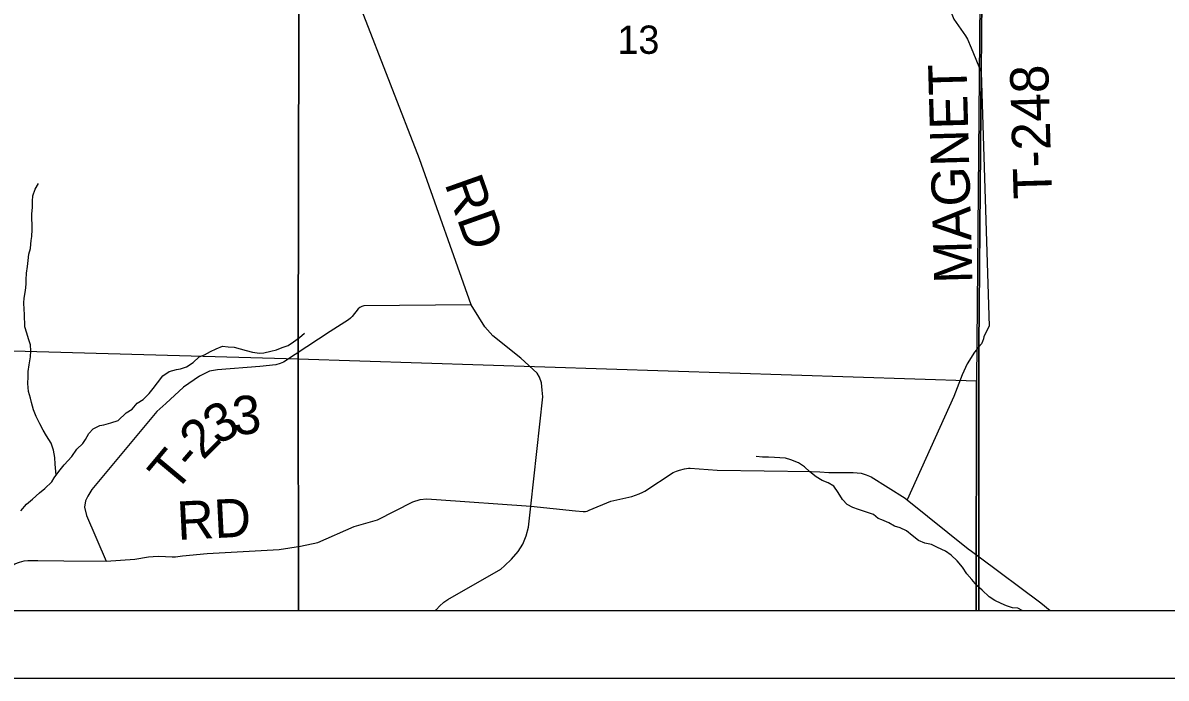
# Model space of a CAD drawing. Extents: x 0 to 34, y 0 to 22.
# Drawn here: x 4.875 to 6.566, y 14 to 14.969 of the extents above; entities that cross this region are included whole.
import ezdxf

# ---------------------------------------------------------------- set-up
doc = ezdxf.new("R2010")
doc.units = 0
for name, color, linetype in [('Default', 7, 'Continuous'), ('SH_Cut_Line', 7, 'Continuous'), ('SH_Data', 7, 'Continuous')]:
    doc.layers.add(name, color=color, linetype=linetype)

msp = doc.modelspace()

# ---------------------------------------------------------------- linework, layer by layer
at = {"layer": 'Default'}
for points in [[(2.1, 17.0156), (2.1, 14.1), (6.2892, 14.1), (6.2892, 14.18), (6.2889, 14.4906), (6.2926, 14.8972), (6.2959, 15.2705), (6.2922, 16.0152), (6.2871, 17.0188)], [(6.3039, 15.2765), (6.2961, 15.27), (6.2499, 15.2316), (6.2115, 15.1924), (6.2056, 15.1844), (6.2019, 15.1787), (6.1996, 15.1727), (6.197, 15.1645), (6.1947, 15.1539), (6.1927, 15.1385), (6.1932, 15.1215), (6.1965, 15.1043), (6.2023, 15.0937), (6.2298, 15.0514), (6.2361, 15.037), (6.2481, 14.9846), (6.2523, 14.9748), (6.2692, 14.9501), (6.2708, 14.9477)], [(5.4857, 14.1), (5.4868, 14.1017), (5.4911, 14.1065), (5.4979, 14.1124), (5.5036, 14.1165), (5.5819, 14.1614), (5.5876, 14.1659), (5.5979, 14.1758), (5.6074, 14.1873), (5.6145, 14.198), (5.6197, 14.2103), (5.6231, 14.2231), (5.6265, 14.2545), (5.6439, 14.416), (5.6432, 14.4258), (5.6421, 14.4369), (5.6393, 14.4453), (5.6355, 14.4513), (5.6116, 14.4735), (5.5702, 14.5066), (5.5582, 14.5198), (5.5493, 14.5341), (5.5383, 14.5523), (5.4615, 14.7681), (5.3761, 14.9891)], [(6.2708, 14.9477), (6.2725, 14.9453), (6.2779, 14.9324), (6.2928, 14.8966), (6.3042, 14.5206), (6.2967, 14.5052), (6.2961, 14.502), (6.2946, 14.498), (6.293, 14.4945), (6.2891, 14.49), (6.2861, 14.4865)], [(4.9242, 14.3003), (4.9229, 14.3167), (4.9224, 14.3266), (4.9203, 14.3372), (4.9167, 14.3474), (4.9101, 14.3584), (4.9051, 14.367), (4.9, 14.3761), (4.8945, 14.387), (4.8906, 14.3968), (4.8878, 14.4078), (4.8862, 14.4142), (4.8834, 14.4241), (4.8821, 14.4358), (4.8827, 14.4457), (4.8829, 14.4537), (4.8843, 14.4636), (4.886, 14.4754), (4.8867, 14.4842), (4.8862, 14.4929), (4.883, 14.502), (4.8806, 14.5103), (4.8778, 14.5197), (4.8775, 14.5384), (4.8767, 14.5452), (4.8762, 14.5554), (4.8768, 14.5623), (4.8786, 14.5733), (4.8796, 14.5828), (4.8798, 14.5893), (4.8805, 14.5992), (4.8818, 14.6091), (4.8825, 14.6178), (4.8839, 14.627), (4.8864, 14.6357), (4.8867, 14.6418), (4.8874, 14.6475), (4.888, 14.6536), (4.8886, 14.6635), (4.8883, 14.687), (4.8889, 14.6965), (4.8892, 14.7057), (4.8898, 14.7137), (4.8931, 14.7232), (4.8979, 14.7316)], [(5.5383, 14.5523), (5.3793, 14.5507), (5.3764, 14.5499), (5.3734, 14.5484), (5.371, 14.5464), (5.362, 14.5349), (5.3596, 14.5326), (5.3567, 14.5303), (5.3295, 14.5129), (5.2607, 14.4676), (5.2556, 14.4656), (5.2493, 14.4633), (5.2253, 14.4608), (5.1629, 14.4563), (5.1508, 14.4539), (5.136, 14.4469), (5.1126, 14.4307), (5.0865, 14.4065), (5.0733, 14.3945), (4.9771, 14.279), (4.9711, 14.2694), (4.9674, 14.2621), (4.966, 14.253), (4.9692, 14.2408), (4.9981, 14.173)], [(4.8718, 14.2476), (4.8801, 14.2576), (4.8891, 14.265), (4.8996, 14.2739), (4.9075, 14.2804), (4.9179, 14.2905), (4.9213, 14.2962), (4.928, 14.3058), (4.9362, 14.3158), (4.9474, 14.3281), (4.9548, 14.3389), (4.9635, 14.3473), (4.9675, 14.3531), (4.9724, 14.3619), (4.9791, 14.3688), (4.9889, 14.3739), (4.9946, 14.3748), (5.0052, 14.3776), (5.0158, 14.3811), (5.0277, 14.3927), (5.0364, 14.3981), (5.0442, 14.4066), (5.0529, 14.4124), (5.0619, 14.4213), (5.0675, 14.4286), (5.0742, 14.4371), (5.082, 14.447), (5.0914, 14.4536), (5.102, 14.4568), (5.1081, 14.4577), (5.1168, 14.4605), (5.1269, 14.4671), (5.1359, 14.4752), (5.1435, 14.4783), (5.1525, 14.4834), (5.1608, 14.4873), (5.1703, 14.4912), (5.1786, 14.4902), (5.1877, 14.4896), (5.2053, 14.4845), (5.2144, 14.482), (5.2251, 14.481), (5.2315, 14.4815), (5.2418, 14.4835), (5.2501, 14.4855), (5.2584, 14.4891), (5.2675, 14.4922), (5.2754, 14.4973), (5.284, 14.5039), (5.2915, 14.5104)], [(6.2861, 14.4865), (6.2855, 14.4858), (6.2825, 14.4822), (6.272, 14.465), (6.2645, 14.4489), (6.2523, 14.4168), (6.183, 14.264)], [(6.3222, 14.1103), (6.3127, 14.1147), (6.3042, 14.1203), (6.2942, 14.13), (6.2861, 14.1371), (6.2788, 14.1461), (6.2715, 14.1544), (6.2649, 14.1641), (6.2571, 14.1735), (6.2483, 14.1818), (6.2398, 14.1877), (6.228, 14.1932), (6.2192, 14.1977), (6.2093, 14.1998), (6.1997, 14.2035), (6.1905, 14.2109), (6.1821, 14.218), (6.1729, 14.2225), (6.1645, 14.2246), (6.1561, 14.2298), (6.1457, 14.2342), (6.14, 14.2364), (6.1331, 14.242), (6.1274, 14.2442), (6.1186, 14.2472), (6.111, 14.2493), (6.1026, 14.2522), (6.0945, 14.2571), (6.0872, 14.2642), (6.081, 14.2747), (6.0748, 14.2838), (6.0663, 14.289), (6.0576, 14.2926), (6.0484, 14.2978), (6.0392, 14.3053), (6.0314, 14.3128), (6.0222, 14.3187), (6.0112, 14.3231), (6.0032, 14.3253), (5.9948, 14.3259), (5.9868, 14.3262), (5.9781, 14.3268), (5.969, 14.3271), (5.9598, 14.3277)], [(5.6265, 14.2545), (5.6925, 14.2474), (5.7037, 14.2467), (5.707, 14.2467), (5.7095, 14.2471), (5.7126, 14.2483), (5.7445, 14.2617), (5.7757, 14.2688), (5.7867, 14.2728), (5.792, 14.275), (5.795, 14.2767), (5.837, 14.3041), (5.8419, 14.3061), (5.8465, 14.3076), (5.8535, 14.3094), (5.8598, 14.3104), (5.8621, 14.3104), (5.9021, 14.3078), (6.0411, 14.3058), (6.054, 14.3052), (6.0673, 14.3042), (6.0815, 14.3041), (6.1031, 14.3042), (6.115, 14.3031), (6.1227, 14.3006), (6.1299, 14.2976), (6.1802, 14.2662), (6.183, 14.264), (6.2734, 14.1913), (6.2782, 14.1878)], [(4.9981, 14.173), (5.0407, 14.1761), (5.0608, 14.1797), (5.0675, 14.1801), (5.0761, 14.1802), (5.0958, 14.1793), (5.1008, 14.1797), (5.1111, 14.181), (5.1476, 14.1844), (5.2541, 14.1904), (5.2857, 14.1953), (5.3111, 14.2005), (5.365, 14.2243), (5.3995, 14.2342), (5.4518, 14.2606), (5.4628, 14.2641), (5.4719, 14.2654), (5.4867, 14.2644), (5.6265, 14.2545)], [(4.6153, 14.1), (4.6671, 14.1106), (4.6819, 14.1126), (4.7744, 14.1208), (4.7867, 14.1267), (4.8024, 14.1341), (4.8629, 14.1689), (4.8701, 14.1715), (4.8766, 14.1733), (4.882, 14.174), (4.8863, 14.1742), (4.8968, 14.1742), (4.9356, 14.1735), (4.9981, 14.173)], [(6.2782, 14.1878), (6.2894, 14.1795), (6.3809, 14.1114), (6.3945, 14.1)], [(6.3531, 14.1), (6.347, 14.1034), (6.339, 14.104), (6.3302, 14.1069), (6.3222, 14.1103)]]:
    msp.add_lwpolyline(points, dxfattribs=at)
for points in [[(6.2892, 14.1), (8.9, 14.1), (8.9, 17.02), (8.2009, 17.0196), (7.211, 17.0191), (7.2045, 17.0191), (6.9328, 17.0189), (6.927, 17.0189), (6.6903, 17.0144), (6.3876, 17.0173), (6.3215, 17.0189), (6.2871, 17.0188), (6.2922, 16.0152), (6.2959, 15.2705), (6.2926, 14.8972), (6.2889, 14.4906), (6.2892, 14.18)], [(4.2566, 15.5062), (5.284, 15.4777), (5.2822, 14.472), (4.2629, 14.5006)], [(5.284, 15.4777), (6.2933, 15.4392), (6.2908, 15.0024), (6.2858, 14.4391), (5.2822, 14.472)], [(6.2854, 14.1), (7.2754, 14.1), (7.2656, 14.9873), (6.2908, 15.0024), (6.2858, 14.4391)], [(4.2648, 14.1), (5.2827, 14.1), (5.2822, 14.472), (4.2629, 14.5006)], [(5.2827, 14.1), (6.2854, 14.1), (6.2858, 14.4391), (5.2822, 14.472)]]:
    msp.add_lwpolyline(points, close=True, dxfattribs=at)
at = {"layer": 'SH_Cut_Line'}
msp.add_lwpolyline([(2.1, 17.0156), (2.1, 14.1), (8.9, 14.1), (8.9, 17.02)], dxfattribs=at)
at = {"layer": 'SH_Data'}
for p, q in [((2.1, 14.1), (8.9, 14.1)), ((2, 14), (9, 14))]:
    msp.add_line(p, q, dxfattribs=at)

# ---------------------------------------------------------------- texts
at = {"layer": 'Default'}
for s, height, rotation, p in [('13', 0.04186, 0, (5.7543, 14.9236)), ('MAGNET', 0.05682, 91.6094, (6.2799, 14.5846)), ('T-248', 0.05682, 91.6848, (6.3975, 14.7098)), ('RD', 0.05682, 289.5223, (5.4983, 14.7318)), ('3', 0.0568, 5.3, (5.1872, 14.3592)), ('3', 0.0568, 29.6455, (5.1628, 14.3438)), ('2', 0.0568, 45.1361, (5.1413, 14.3215)), ('T', 0.0568, 50.1769, (5.0997, 14.2722)), ('-', 0.0568, 49.204, (5.1268, 14.3046)), ('RD', 0.05682, 2.9371, (5.1041, 14.2043))]:
    msp.add_text(s, height=height, rotation=rotation, dxfattribs=at).set_placement(p)

doc.saveas('drawing.dxf')
